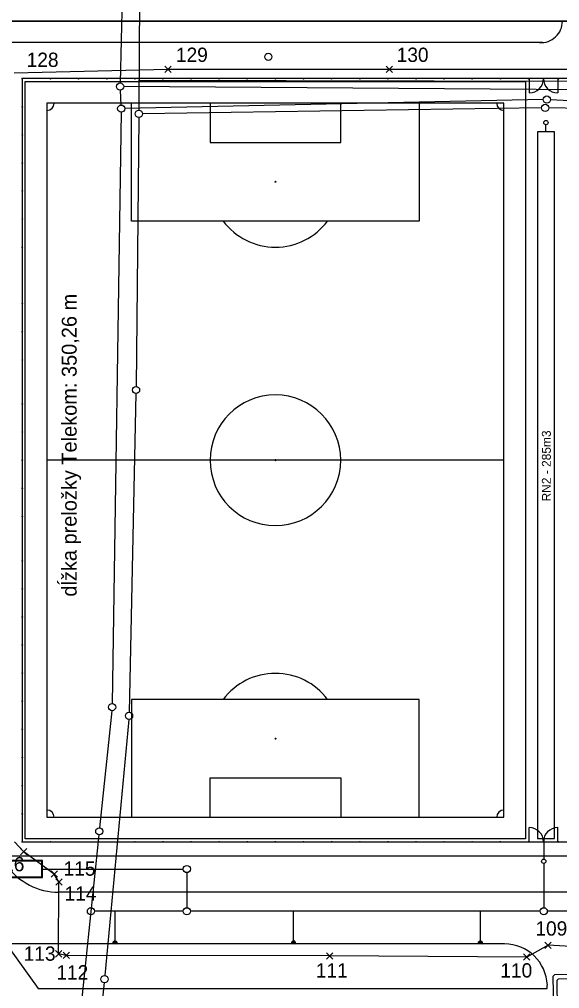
# Model space of a CAD drawing. Extents: x -264205 to -263744, y -1242450 to -1242050.
# Drawn here: x -264118.5 to -264042.8, y -1242315 to -1242179.2 of the extents above; entities that cross this region are included whole.
import ezdxf

# ---------------------------------------------------------------- set-up
doc = ezdxf.new("R2010")
doc.units = 0
for name, color, linetype in [('KFA_63-1_TELEKOM_PRELOZKA', 7, 'Continuous'), ('KFA_BODY_CISLO', 7, 'Continuous'), ('KFA_BODY_SYMBOL', 7, 'Continuous'), ('KFA_JESTV_IS_DSP', 7, 'Continuous'), ('KFA_SITUACIA_DSP', 7, 'Continuous'), ('POPIS', 7, 'Continuous')]:
    doc.layers.add(name, color=color, linetype=linetype)

msp = doc.modelspace()

# ---------------------------------------------------------------- linework, layer by layer
at = {"layer": 'KFA_63-1_TELEKOM_PRELOZKA'}
for points in [[(-264119.22, -1242186.72), (-264097.68, -1242186.22), (-264066.65, -1242186.22), (-264036.88, -1242186.22), (-264030.42, -1242186.25), (-264029.97, -1242185.57), (-264029.87, -1242182.08)], [(-264031.69, -1242316.63), (-264035.64, -1242310.62), (-264036.48, -1242309.38), (-264044.43, -1242308.91), (-264047.41, -1242310.56), (-264075.03, -1242310.4), (-264111.92, -1242310.33), (-264112.99, -1242310.11), (-264112.94, -1242300.05), (-264113.6, -1242298.94), (-264117.86, -1242295.81), (-264119.15, -1242294.42)]]:
    msp.add_lwpolyline(points, dxfattribs=at)
at = {"layer": 'KFA_BODY_SYMBOL'}
for p, q in [((-264098.12, -1242186.66), (-264097.24, -1242185.77)), ((-264097.24, -1242186.66), (-264098.12, -1242185.77)), ((-264067.1, -1242186.66), (-264066.21, -1242185.78)), ((-264066.21, -1242186.66), (-264067.1, -1242185.78)), ((-264097.68, -1242186.22), (-264097.68, -1242186.22)), ((-264066.65, -1242186.22), (-264066.65, -1242186.22)), ((-264118.31, -1242296.25), (-264117.42, -1242295.37)), ((-264117.42, -1242296.25), (-264118.31, -1242295.37)), ((-264117.86, -1242295.81), (-264117.86, -1242295.81)), ((-264114.04, -1242299.38), (-264113.16, -1242298.5)), ((-264113.16, -1242299.38), (-264114.04, -1242298.5)), ((-264113.6, -1242298.94), (-264113.6, -1242298.94)), ((-264113.38, -1242300.49), (-264112.5, -1242299.61)), ((-264112.5, -1242300.49), (-264113.38, -1242299.61)), ((-264112.94, -1242300.05), (-264112.94, -1242300.05)), ((-264044.87, -1242309.35), (-264043.99, -1242308.47)), ((-264043.99, -1242309.35), (-264044.87, -1242308.47)), ((-264044.43, -1242308.91), (-264044.43, -1242308.91)), ((-264113.43, -1242310.56), (-264112.55, -1242309.67)), ((-264112.55, -1242310.56), (-264113.43, -1242309.67)), ((-264112.99, -1242310.11), (-264112.99, -1242310.11)), ((-264112.36, -1242310.77), (-264111.48, -1242309.88)), ((-264111.48, -1242310.77), (-264112.36, -1242309.88)), ((-264111.92, -1242310.33), (-264111.92, -1242310.33)), ((-264075.47, -1242310.84), (-264074.59, -1242309.96)), ((-264074.59, -1242310.84), (-264075.47, -1242309.96)), ((-264075.03, -1242310.4), (-264075.03, -1242310.4)), ((-264047.85, -1242311), (-264046.97, -1242310.12)), ((-264046.97, -1242311), (-264047.85, -1242310.12)), ((-264047.41, -1242310.56), (-264047.41, -1242310.56))]:
    msp.add_line(p, q, dxfattribs=at)
at = {"layer": 'KFA_JESTV_IS_DSP'}
for p, q in [((-264103.36, -1242140.62), (-264104.36, -1242188.14)), ((-264101.42, -1242142.58), (-264101.75, -1242191.96)), ((-264014.6, -1242189.3), (-264103.87, -1242188.64)), ((-264014.74, -1242187.97), (-264101.79, -1242187.81)), ((-264104.37, -1242189.14), (-264104.25, -1242191.23)), ((-264045.1, -1242190.47), (-264103.72, -1242191.72)), ((-263970.37, -1242194.6), (-264044.1, -1242190.48)), ((-264104.23, -1242192.23), (-264105.48, -1242275.06)), ((-264045.33, -1242191.64), (-264101.25, -1242192.45)), ((-263970.54, -1242192.88), (-264044.33, -1242191.64)), ((-264101.76, -1242192.96), (-264102.14, -1242230.64)), ((-264102.15, -1242231.64), (-264103.11, -1242276.28)), ((-264105.54, -1242276.06), (-264107.24, -1242292.46)), ((-264103.16, -1242277.28), (-264106.52, -1242313.16)), ((-264107.35, -1242293.45), (-264113.93, -1242356.84)), ((-264043.54, -1242313.06), (-264043.78, -1242313.27)), ((-264043.78, -1242313.27), (-264043.67, -1242317.93)), ((-264037.28, -1242312.92), (-264043.54, -1242313.06)), ((-264043.16, -1242313.81), (-264042.95, -1242313.61)), ((-264042.95, -1242313.61), (-264037.23, -1242313.51)), ((-264106.61, -1242314.15), (-264111.27, -1242359.73)), ((-264043.1, -1242317.89), (-264043.16, -1242313.81))]:
    msp.add_line(p, q, dxfattribs=at)
for centre in [(-264083.61, -1242184.48), (-264104.37, -1242188.64), (-264044.6, -1242190.46), (-264104.22, -1242191.73), (-264044.83, -1242191.63), (-264101.75, -1242192.46), (-264102.14, -1242231.14), (-264105.49, -1242275.56), (-264103.12, -1242276.78), (-264107.29, -1242292.96), (-264106.56, -1242313.66)]:
    msp.add_circle(centre, 0.5, dxfattribs=at)
at = {"layer": 'KFA_SITUACIA_DSP'}
for p, q in [((-264077.23, -1242179.48), (-264131.57, -1242179.48)), ((-264131.57, -1242179.48), (-263959.47, -1242179.48)), ((-263959.47, -1242179.48), (-264131.57, -1242179.48)), ((-263959.47, -1242179.48), (-264077.23, -1242179.48)), ((-264045.2, -1242182.48), (-264131.57, -1242182.48)), ((-264118.01, -1242187.53), (-264118.13, -1242187.53)), ((-264118.07, -1242187.59), (-264118.07, -1242187.47)), ((-263972.07, -1242187.53), (-264118.07, -1242187.53)), ((-264118.07, -1242187.53), (-264118.07, -1242294.43)), ((-264114.07, -1242187.53), (-264114.19, -1242187.53)), ((-264114.13, -1242187.59), (-264114.13, -1242187.47)), ((-264110.13, -1242187.53), (-264110.25, -1242187.53)), ((-264110.19, -1242187.59), (-264110.19, -1242187.47)), ((-264106.19, -1242187.53), (-264106.31, -1242187.53)), ((-264106.25, -1242187.59), (-264106.25, -1242187.47)), ((-264102.25, -1242187.53), (-264102.37, -1242187.53)), ((-264102.31, -1242187.59), (-264102.31, -1242187.47)), ((-264098.31, -1242187.53), (-264098.43, -1242187.53)), ((-264098.37, -1242187.59), (-264098.37, -1242187.47)), ((-264094.37, -1242187.53), (-264094.49, -1242187.53)), ((-264094.43, -1242187.59), (-264094.43, -1242187.47)), ((-264090.44, -1242187.53), (-264090.56, -1242187.53)), ((-264090.5, -1242187.59), (-264090.5, -1242187.47)), ((-264086.5, -1242187.53), (-264086.62, -1242187.53)), ((-264086.56, -1242187.59), (-264086.56, -1242187.47)), ((-264082.56, -1242187.53), (-264082.68, -1242187.53)), ((-264082.62, -1242187.59), (-264082.62, -1242187.47)), ((-264078.62, -1242187.53), (-264078.74, -1242187.53)), ((-264078.68, -1242187.59), (-264078.68, -1242187.47)), ((-264074.68, -1242187.53), (-264074.8, -1242187.53)), ((-264074.74, -1242187.59), (-264074.74, -1242187.47)), ((-264070.74, -1242187.53), (-264070.86, -1242187.53)), ((-264070.8, -1242187.59), (-264070.8, -1242187.47)), ((-264066.8, -1242187.53), (-264066.92, -1242187.53)), ((-264066.86, -1242187.59), (-264066.86, -1242187.47)), ((-264062.86, -1242187.53), (-264062.98, -1242187.53)), ((-264062.92, -1242187.59), (-264062.92, -1242187.47)), ((-264058.92, -1242187.53), (-264059.04, -1242187.53)), ((-264058.98, -1242187.59), (-264058.98, -1242187.47)), ((-264054.99, -1242187.53), (-264055.11, -1242187.53)), ((-264055.05, -1242187.59), (-264055.05, -1242187.47)), ((-264051.05, -1242187.53), (-264051.17, -1242187.53)), ((-264051.11, -1242187.59), (-264051.11, -1242187.47)), ((-264047.11, -1242187.53), (-264047.23, -1242187.53)), ((-264047.17, -1242187.59), (-264047.17, -1242187.47)), ((-264047.07, -1242187.53), (-264047.07, -1242189.53)), ((-264044.57, -1242187.53), (-264045.57, -1242187.53)), ((-264043.07, -1242187.53), (-264043.07, -1242189.53)), ((-264042.91, -1242187.53), (-264043.03, -1242187.53)), ((-264042.97, -1242187.59), (-264042.97, -1242187.47)), ((-264118.07, -1242191.41), (-264118.07, -1242191.53)), ((-264050.62, -1242190.98), (-264114.62, -1242190.98)), ((-264114.62, -1242190.98), (-264114.62, -1242290.98)), ((-264102.78, -1242207.48), (-264102.78, -1242190.98)), ((-264091.78, -1242190.98), (-264091.78, -1242196.48)), ((-264073.46, -1242196.48), (-264073.46, -1242190.98)), ((-264062.46, -1242190.98), (-264062.46, -1242207.48)), ((-264050.62, -1242290.98), (-264050.62, -1242190.98)), ((-264204.69, -1242191.48), (-264115.87, -1242314.98)), ((-264118.01, -1242191.47), (-264118.13, -1242191.47)), ((-264044.73, -1242194.98), (-264044.73, -1242193.98)), ((-264118.01, -1242195.41), (-264118.13, -1242195.41)), ((-264118.07, -1242195.35), (-264118.07, -1242195.47)), ((-264043.53, -1242194.98), (-264045.93, -1242194.98)), ((-264045.93, -1242194.98), (-264045.93, -1242293.98)), ((-264043.53, -1242293.98), (-264043.53, -1242194.98)), ((-264091.78, -1242196.48), (-264073.46, -1242196.48)), ((-264118.01, -1242199.34), (-264118.13, -1242199.34)), ((-264118.07, -1242199.28), (-264118.07, -1242199.4)), ((-264118.01, -1242203.28), (-264118.13, -1242203.28)), ((-264118.07, -1242203.22), (-264118.07, -1242203.34)), ((-264118.01, -1242207.22), (-264118.13, -1242207.22)), ((-264118.07, -1242207.16), (-264118.07, -1242207.28)), ((-264062.46, -1242207.48), (-264102.78, -1242207.48)), ((-264118.01, -1242211.16), (-264118.13, -1242211.16)), ((-264118.07, -1242211.1), (-264118.07, -1242211.22)), ((-264118.01, -1242219.03), (-264118.13, -1242219.03)), ((-264118.07, -1242218.97), (-264118.07, -1242219.09)), ((-264118.01, -1242222.97), (-264118.13, -1242222.97)), ((-264118.07, -1242222.91), (-264118.07, -1242223.03)), ((-264118.01, -1242226.91), (-264118.13, -1242226.91)), ((-264118.07, -1242226.85), (-264118.07, -1242226.97)), ((-264118.01, -1242233.11), (-264118.13, -1242233.11)), ((-264118.07, -1242233.05), (-264118.07, -1242233.17)), ((-264118.01, -1242237.04), (-264118.13, -1242237.04)), ((-264118.07, -1242236.98), (-264118.07, -1242237.1)), ((-264118.01, -1242240.98), (-264118.13, -1242240.98)), ((-264118.07, -1242241.04), (-264118.07, -1242240.92)), ((-264050.62, -1242240.98), (-264114.62, -1242240.98)), ((-264118.01, -1242244.92), (-264118.13, -1242244.92)), ((-264118.07, -1242244.98), (-264118.07, -1242244.86)), ((-264118.01, -1242248.86), (-264118.13, -1242248.86)), ((-264118.07, -1242248.92), (-264118.07, -1242248.8)), ((-264118.01, -1242255.06), (-264118.13, -1242255.06)), ((-264118.07, -1242255.12), (-264118.07, -1242255)), ((-264118.01, -1242258.99), (-264118.13, -1242258.99)), ((-264118.07, -1242259.05), (-264118.07, -1242258.93)), ((-264118.01, -1242262.93), (-264118.13, -1242262.93)), ((-264118.07, -1242262.99), (-264118.07, -1242262.87)), ((-264118.01, -1242266.87), (-264118.13, -1242266.87)), ((-264118.07, -1242266.93), (-264118.07, -1242266.81)), ((-264118.01, -1242270.81), (-264118.13, -1242270.81)), ((-264118.07, -1242270.87), (-264118.07, -1242270.75)), ((-264118.01, -1242274.74), (-264118.13, -1242274.74)), ((-264118.07, -1242274.8), (-264118.07, -1242274.68)), ((-264062.46, -1242274.48), (-264102.78, -1242274.48)), ((-264102.78, -1242274.48), (-264102.78, -1242290.98)), ((-264062.46, -1242290.98), (-264062.46, -1242274.48)), ((-264118.01, -1242278.68), (-264118.13, -1242278.68)), ((-264118.07, -1242278.74), (-264118.07, -1242278.62)), ((-264118.01, -1242282.62), (-264118.13, -1242282.62)), ((-264118.07, -1242282.68), (-264118.07, -1242282.56)), ((-264091.78, -1242290.98), (-264091.78, -1242285.48)), ((-264091.78, -1242285.48), (-264073.46, -1242285.48)), ((-264073.46, -1242285.48), (-264073.46, -1242290.98)), ((-264118.01, -1242286.56), (-264118.13, -1242286.56)), ((-264118.07, -1242286.62), (-264118.07, -1242286.5)), ((-264118.01, -1242290.49), (-264118.13, -1242290.49)), ((-264118.07, -1242290.55), (-264118.07, -1242290.43)), ((-264114.62, -1242290.98), (-264050.62, -1242290.98)), ((-264047.07, -1242294.43), (-264047.07, -1242292.43)), ((-264043.07, -1242294.43), (-264043.07, -1242292.43)), ((-264118.01, -1242294.43), (-264118.13, -1242294.43)), ((-264118.07, -1242294.49), (-264118.07, -1242294.37)), ((-264118.07, -1242294.43), (-264045.12, -1242294.43)), ((-264114.07, -1242294.43), (-264114.19, -1242294.43)), ((-264114.13, -1242294.49), (-264114.13, -1242294.37)), ((-264102.25, -1242294.43), (-264102.37, -1242294.43)), ((-264102.31, -1242294.49), (-264102.31, -1242294.37)), ((-264098.31, -1242294.43), (-264098.43, -1242294.43)), ((-264098.37, -1242294.49), (-264098.37, -1242294.37)), ((-264094.37, -1242294.43), (-264094.49, -1242294.43)), ((-264094.43, -1242294.49), (-264094.43, -1242294.37)), ((-264090.44, -1242294.43), (-264090.56, -1242294.43)), ((-264090.5, -1242294.49), (-264090.5, -1242294.37)), ((-264086.5, -1242294.43), (-264086.62, -1242294.43)), ((-264086.56, -1242294.49), (-264086.56, -1242294.37)), ((-264082.56, -1242294.43), (-264082.68, -1242294.43)), ((-264082.62, -1242294.49), (-264082.62, -1242294.37)), ((-264078.62, -1242294.43), (-264078.74, -1242294.43)), ((-264078.68, -1242294.49), (-264078.68, -1242294.37)), ((-264074.68, -1242294.43), (-264074.8, -1242294.43)), ((-264074.74, -1242294.49), (-264074.74, -1242294.37)), ((-264070.74, -1242294.43), (-264070.86, -1242294.43)), ((-264070.8, -1242294.49), (-264070.8, -1242294.37)), ((-264066.8, -1242294.43), (-264066.92, -1242294.43)), ((-264066.86, -1242294.49), (-264066.86, -1242294.37)), ((-264062.86, -1242294.43), (-264062.98, -1242294.43)), ((-264062.92, -1242294.49), (-264062.92, -1242294.37)), ((-264058.92, -1242294.43), (-264059.04, -1242294.43)), ((-264058.98, -1242294.49), (-264058.98, -1242294.37)), ((-264054.99, -1242294.43), (-264055.11, -1242294.43)), ((-264055.05, -1242294.49), (-264055.05, -1242294.37)), ((-264051.05, -1242294.43), (-264051.17, -1242294.43)), ((-264051.11, -1242294.49), (-264051.11, -1242294.37)), ((-264047.11, -1242294.43), (-264047.23, -1242294.43)), ((-264047.17, -1242294.49), (-264047.17, -1242294.37)), ((-264045.93, -1242293.98), (-264043.53, -1242293.98)), ((-264045.57, -1242294.43), (-264044.57, -1242294.43)), ((-264045.12, -1242294.43), (-263972.07, -1242294.43)), ((-264045.02, -1242293.98), (-264045.03, -1242296.85)), ((-264042.91, -1242294.43), (-264043.03, -1242294.43)), ((-264042.97, -1242294.49), (-264042.97, -1242294.37)), ((-264115.25, -1242297.04), (-264120.15, -1242297.04)), ((-264115.35, -1242297.14), (-264120.05, -1242297.14)), ((-264115.35, -1242299.34), (-264115.35, -1242297.14)), ((-264115.25, -1242299.44), (-264115.25, -1242297.04)), ((-264115.25, -1242298.24), (-264095.53, -1242298.24)), ((-264045.03, -1242297.45), (-264045.03, -1242303.65)), ((-264120.15, -1242299.44), (-264115.25, -1242299.44)), ((-264120.05, -1242299.34), (-264115.35, -1242299.34)), ((-264095.03, -1242298.74), (-264095.03, -1242303.65)), ((-263971.07, -1242301.48), (-264112.96, -1242301.48)), ((-264095.53, -1242304.15), (-264107.96, -1242304.15)), ((-264105.08, -1242308.24), (-264105.08, -1242304.15)), ((-264045.53, -1242304.15), (-264094.53, -1242304.15)), ((-264080.08, -1242308.24), (-264080.08, -1242304.15)), ((-264053.91, -1242308.24), (-264053.91, -1242304.15)), ((-264004.4, -1242304.15), (-264044.53, -1242304.15)), ((-264050.53, -1242308.73), (-264119.75, -1242308.73)), ((-264105.33, -1242308.44), (-264104.83, -1242308.44)), ((-264105.33, -1242308.73), (-264105.33, -1242308.44)), ((-264105.33, -1242308.44), (-264104.83, -1242308.73)), ((-264105.33, -1242308.44), (-264104.83, -1242308.73)), ((-264104.83, -1242308.44), (-264105.33, -1242308.44)), ((-264104.83, -1242308.73), (-264105.33, -1242308.73)), ((-264104.83, -1242308.44), (-264104.83, -1242308.73)), ((-264104.83, -1242308.73), (-264104.83, -1242308.44)), ((-264080.33, -1242308.44), (-264079.83, -1242308.44)), ((-264080.33, -1242308.73), (-264080.33, -1242308.44)), ((-264080.33, -1242308.44), (-264079.83, -1242308.73)), ((-264080.33, -1242308.44), (-264079.83, -1242308.73)), ((-264079.83, -1242308.44), (-264080.33, -1242308.44)), ((-264079.83, -1242308.73), (-264080.33, -1242308.73)), ((-264079.83, -1242308.44), (-264079.83, -1242308.73)), ((-264079.83, -1242308.73), (-264079.83, -1242308.44)), ((-264054.16, -1242308.44), (-264053.66, -1242308.44)), ((-264054.16, -1242308.73), (-264054.16, -1242308.44)), ((-264054.16, -1242308.44), (-264053.66, -1242308.73)), ((-264054.16, -1242308.44), (-264053.66, -1242308.73)), ((-264053.66, -1242308.44), (-264054.16, -1242308.44)), ((-264053.66, -1242308.73), (-264054.16, -1242308.73)), ((-264053.66, -1242308.44), (-264053.66, -1242308.73)), ((-264053.66, -1242308.73), (-264053.66, -1242308.44)), ((-264115.89, -1242314.98), (-264044.53, -1242314.98)), ((-264044.53, -1242314.98), (-264044.53, -1242314.48))]:
    msp.add_line(p, q, dxfattribs=at)
msp.add_lwpolyline([(-264117.67, -1242187.93), (-264047.57, -1242187.93), (-264047.57, -1242294.03), (-264117.67, -1242294.03)], close=True, dxfattribs=at)
msp.add_lwpolyline([(-263965.14, -1242296.43), (-264120.02, -1242296.43), (-264120.28, -1242296.43)], dxfattribs=at)
for centre, radius in [((-264118.07, -1242187.53), 0.06), ((-264114.13, -1242187.53), 0.06), ((-264110.19, -1242187.53), 0.06), ((-264106.25, -1242187.53), 0.06), ((-264102.31, -1242187.53), 0.06), ((-264098.37, -1242187.53), 0.06), ((-264094.43, -1242187.53), 0.06), ((-264090.5, -1242187.53), 0.06), ((-264086.56, -1242187.53), 0.06), ((-264082.62, -1242187.53), 0.06), ((-264078.68, -1242187.53), 0.06), ((-264074.74, -1242187.53), 0.06), ((-264070.8, -1242187.53), 0.06), ((-264066.86, -1242187.53), 0.06), ((-264062.92, -1242187.53), 0.06), ((-264058.98, -1242187.53), 0.06), ((-264055.05, -1242187.53), 0.06), ((-264051.11, -1242187.53), 0.06), ((-264047.17, -1242187.53), 0.06), ((-264042.97, -1242187.53), 0.06), ((-264118.07, -1242191.47), 0.06), ((-264044.73, -1242193.68), 0.3), ((-264118.07, -1242195.41), 0.06), ((-264118.07, -1242199.34), 0.06), ((-264082.62, -1242201.98), 0.06), ((-264118.07, -1242203.28), 0.06), ((-264118.07, -1242207.22), 0.06), ((-264118.07, -1242211.16), 0.06), ((-264118.07, -1242219.03), 0.06), ((-264118.07, -1242222.97), 0.06), ((-264118.07, -1242226.91), 0.06), ((-264118.07, -1242233.11), 0.06), ((-264118.07, -1242237.04), 0.06), ((-264118.07, -1242240.98), 0.06), ((-264118.07, -1242244.92), 0.06), ((-264118.07, -1242248.86), 0.06), ((-264118.07, -1242255.06), 0.06), ((-264118.07, -1242258.99), 0.06), ((-264118.07, -1242262.93), 0.06), ((-264118.07, -1242266.87), 0.06), ((-264118.07, -1242270.81), 0.06), ((-264118.07, -1242274.74), 0.06), ((-264118.07, -1242278.68), 0.06), ((-264082.62, -1242279.98), 0.06), ((-264118.07, -1242282.62), 0.06), ((-264118.07, -1242286.56), 0.06), ((-264118.07, -1242290.49), 0.06), ((-264118.07, -1242294.43), 0.06), ((-264114.13, -1242294.43), 0.06), ((-264102.31, -1242294.43), 0.06), ((-264098.37, -1242294.43), 0.06), ((-264094.43, -1242294.43), 0.06), ((-264090.5, -1242294.43), 0.06), ((-264086.56, -1242294.43), 0.06), ((-264082.62, -1242294.43), 0.06), ((-264078.68, -1242294.43), 0.06), ((-264074.74, -1242294.43), 0.06), ((-264070.8, -1242294.43), 0.06), ((-264066.86, -1242294.43), 0.06), ((-264062.92, -1242294.43), 0.06), ((-264058.98, -1242294.43), 0.06), ((-264055.05, -1242294.43), 0.06), ((-264051.11, -1242294.43), 0.06), ((-264047.17, -1242294.43), 0.06), ((-264042.97, -1242294.43), 0.06), ((-264045.03, -1242297.15), 0.3), ((-264095.03, -1242298.24), 0.5), ((-264108.46, -1242304.15), 0.5), ((-264095.03, -1242304.15), 0.5), ((-264045.03, -1242304.15), 0.5), ((-264105.08, -1242308.34), 0.1), ((-264080.08, -1242308.34), 0.1), ((-264053.91, -1242308.34), 0.1)]:
    msp.add_circle(centre, radius, dxfattribs=at)
for centre, radius, start, end in [((-264045.41, -1242179.5), 2.99, 266.0314, 0.25), ((-264047.07, -1242187.53), 2, 270, 360), ((-264043.07, -1242187.53), 2, 180, 270), ((-264114.62, -1242190.98), 1, 270, 360), ((-264050.62, -1242190.98), 1, 180, 270), ((-264082.62, -1242201.98), 0.0303, 90, 270), ((-264082.62, -1242201.98), 0.0303, 270, 90), ((-264082.62, -1242201.98), 9.15, 216.9482, 323.0518), ((-264082.62, -1242240.98), 9.15, 360, 180), ((-264082.62, -1242240.98), 9.15, 180, 360), ((-264082.62, -1242240.98), 0.0605, 90, 270), ((-264082.62, -1242240.98), 0.0605, 270, 90), ((-264082.62, -1242279.98), 9.15, 36.9482, 143.0518), ((-264082.62, -1242279.98), 0.0303, 90, 270), ((-264082.62, -1242279.98), 0.0303, 270, 90), ((-264114.62, -1242290.98), 1, 0, 90), ((-264050.62, -1242290.98), 1, 90, 180), ((-264047.07, -1242294.43), 2, 0, 90), ((-264043.07, -1242294.43), 2, 90, 180), ((-264112.96, -1242292.48), 9, 215.724, 270), ((-264050.56, -1242314.77), 6.04, 2.7254, 89.7124)]:
    msp.add_arc(centre, radius, start, end, dxfattribs=at)

# ---------------------------------------------------------------- texts
at = {"layer": 'KFA_BODY_CISLO'}
for s, p in [('129', (-264096.55, -1242185.19)), ('130', (-264065.63, -1242185.19)), ('128', (-264117.46, -1242185.89)), ('116', (-264122.24, -1242298.55)), ('115', (-264112.28, -1242299.17)), ('114', (-264112.14, -1242302.66)), ('109', (-264046.2, -1242307.56)), ('113', (-264117.88, -1242311.08)), ('112', (-264113.3, -1242313.71)), ('111', (-264076.96, -1242313.44)), ('110', (-264051.11, -1242313.43))]:
    msp.add_text(s, height=2, dxfattribs=at).set_placement(p)
at = {"layer": 'KFA_SITUACIA_DSP'}
msp.add_text('RN2 - 285m3', height=1.25, rotation=90, dxfattribs=at).set_placement((-264044.04, -1242246.75))
at = {"layer": 'POPIS'}
msp.add_text('dĺžka preložky Telekom: 350,26 m', height=2.09, rotation=90, dxfattribs=at).set_placement((-264110.46, -1242260.08))

doc.saveas('drawing.dxf')
